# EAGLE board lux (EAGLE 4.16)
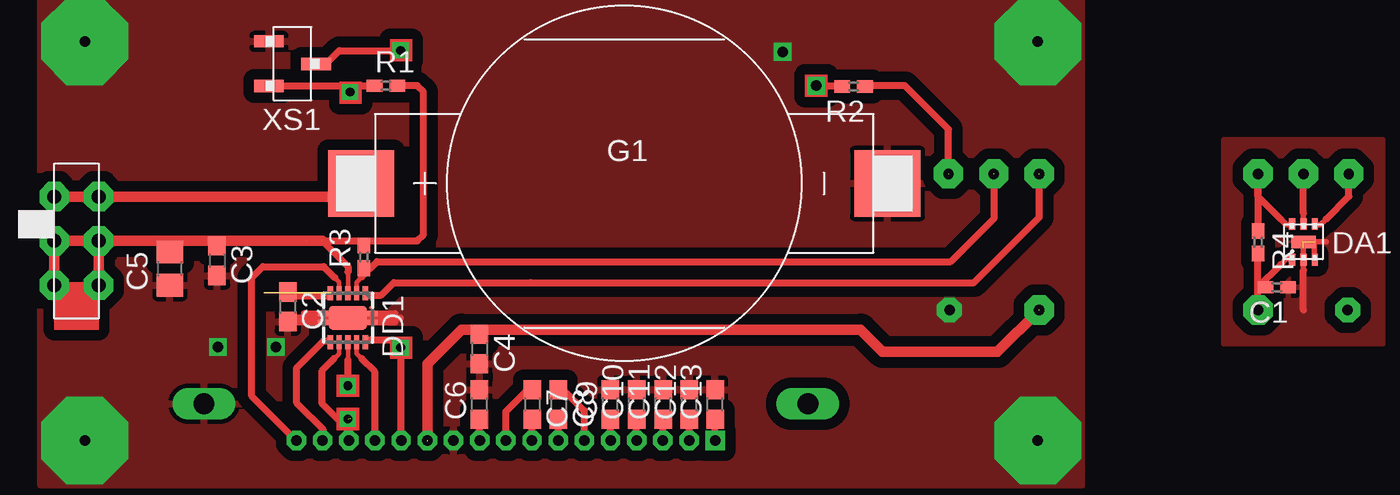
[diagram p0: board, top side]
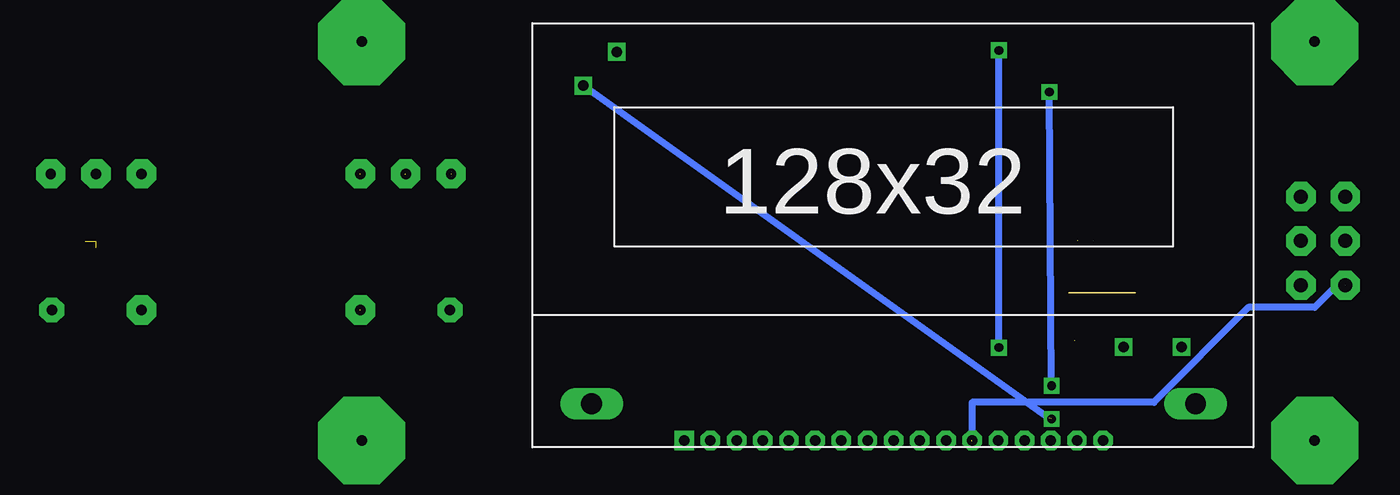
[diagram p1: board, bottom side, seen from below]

Size 3.81 x 0 mm. Coordinates in mm from the lower left corner, seen from the top.
Outline: 0,0 3.81,0
Copper layers (1*16): Top 0.035mm / dielectric 1.5mm / Bottom 0.035mm
Design rules "default": minimum track width 10mil, minimum drill 24mil, track to track 8mil, track to pad 8mil, pad to pad 8mil, via to via 8mil, smd to smd 8mil, copper to edge 40mil, drill to drill 8mil, minimum pad ring 10mil, minimum via ring 8mil, stop-mask expansion 4mil, vias tented up to drill 0mil, thermal gap 10mil

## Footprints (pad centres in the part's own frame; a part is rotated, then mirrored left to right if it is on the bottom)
C0402 = smd 0.9 x 0.7: 1 -0.65,0; 2 0.65,0
C0603 = smd 1.1 x 1: 1 -0.85,0; 2 0.85,0
C0805 = smd 1.3 x 1.5: 1 -0.95,0; 2 0.95,0
MLP11 = smd 0.8 x 0.3: 1 -1.4,1; 2 -1.4,0.5; 3 -1.4,0; 4 -1.4,-0.5; 5 -1.4,-1; 6 1.4,-1; 7 1.4,-0.5; 8 1.4,0; 9 1.4,0.5; 10 1.4,1 | smd 1.36 x 2.2: G 0,0 | smd 0.3 x 0.8: G1 -0.25,1.3; G2 0.25,1.3; G3 -0.25,-1.3; G4 0.25,-1.3
C12832 = drill 0.6 square: 1 -12,0 | drill 0.6 octagon: 2 -10.5,0; 3 -9,0; 4 -7.5,0; 5 -6,0; 6 -4.5,0; 7 -3,0; 8 -1.5,0; 9 0,0; 10 1.5,0; 11 3,0; 12 4.5,0; 13 6,0; 14 7.5,0; 15 9,0; 16 10.5,0; 17 12,0 | drill 1.2 long: 18 17.3,2.1; 19 -17.3,2.1
6UTDFN = smd 0.68 x 0.36: P$1 -1.025,0.65; P$2 -1.025,0; P$3 -1.025,-0.65; P$4 1.025,-0.65; P$5 1.025,0; P$6 1.025,0.65 | smd 0.71 x 1.4: P$7 0,0
CR2032 = smd 3.8 x 3.8: P$2 0,15.081; P$3 0,-15.081
SLIDER3 = drill 0.8 pad 1.676 octagon: P$1 0,1.27; P$2 -2.54,1.27; P$3 2.54,1.27; P$4 2.54,-1.27; P$5 0,-1.27; P$6 -2.54,-1.27
HEADER3S = smd 0.7 x 1.7: P$1 1.27,1.35; P$3 -1.28,1.35; P$4 -0.03,-1.35

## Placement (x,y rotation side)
C1  GND  [C0402]  not placed on the board
C2  [C0603]  1.35,-0.79 270 top
C3  [C0603]  -2.7,1.85 270 top
C4  [C0603]  not placed on the board
C5  [C0805]  not placed on the board
C6  [C0603]  not placed on the board
C7  [C0603]  not placed on the board
C8  [C0603]  not placed on the board
C9  [C0603]  not placed on the board
C10  [C0603]  not placed on the board
C11  [C0603]  not placed on the board
C12  [C0603]  not placed on the board
C13  [C0603]  not placed on the board
DD1  [MLP11]  4.8,-1.43 270 top
E$1  [C12832]  13.85,-8.45 0 bottom  (outside the outline)
E$12  [6UTDFN]  not placed on the board
E$43  [CR2032]  not placed on the board
E$44  [SLIDER3]  -10.76,2.98 270 top  (outside the outline)
R1  [C0402]  not placed on the board
R2  [C0402]  not placed on the board
R3  [C0402]  5.71,2.06 90 top
R4  [C0402]  not placed on the board
XS1  [HEADER3S]  not placed on the board

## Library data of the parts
C1-C13 R1-R4 = rcl
DD1 = silabs
E$1 = display-lcd
E$12 = maxim
E$43 E$44 XS1 = sb

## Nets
GND: C2.2 C3.2 C4.2 C5.1 C6.2 C9.2 C10.2 C11.2 C12.2 C13.2 E$1.11 E$1.18 E$43.P$2 XS1.P$1
GND2: C1.1 E$12.P$7
PWR: E$44.P$3 E$44.P$4
S$1: E$1.9
S$22: XS1.P$3

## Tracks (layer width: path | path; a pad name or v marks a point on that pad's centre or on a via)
GND  (via drill 0.6, 0.6 pad 1.42, 0.6 pad 5)
  Top 0.406: 7.48,-1.67 4.8,-1.67 1.86,-1.67 | 1.59,-1.43 7.82,-1.43 | 2.3,-1.19 7.48,-1.19
  other vias: -10.28,-8.45 39.27,-0.98 -10.28,14.41 44.33,-8.45 44.33,14.41 -2.66,-3.1 0.67,-3.1 29.73,13.81
  pour Top (isolate 0.61): 46.87,-10.99 46.87,16.95 -12.82,16.95 -12.82,-10.99
GND2  (2 unrouted)
  Top 0.305: 60.19,2.92 60.19,1.77 | 59.55,1.3 59.55,2.6 | 59.16,2.92 60.85,2.92
  Top 0.406: 59.55,-0.98 59.55,1.3
  pour Top (isolate 0.61): 64.1,-2.93 55,-2.93 55,8.77 64.1,8.77
GND3  (via drill 0.6 pad 1.42)
  other vias: 62.09,-0.98
PWR  (via drill 0.6 pad 1.68)  (5 unrouted)
  Top 0.254: 4.8,1.19 4.8,-0.28
  Top 0.406: 7.46,11.87 8.77,11.87 9.13,11.51 9.13,3.33 8.77,2.98 | 4.8,1.51 4.8,1.19 | 8.77,2.98 | 3.29,2.98 8.77,2.98 | 4.8,1.51 | 4.8,1.51 3.33,2.98 | E$44.P$4 E$44.P$3
  Top 0.61: 44.41,-0.99 42.03,-3.37 35.44,-3.37 34.17,-2.1 11.31,-2.1 9.37,-4.05 9.37,-8.45 | 3.33,2.98 2.42,2.98 -9.49,2.98 | E$44.P$3 -9.49,2.98 | -9.49,2.98 -12.03,2.98 E$44.P$4
  Bottom 0.406: 9.37,-8.49 9.37,-7.98 9.37,-6.27 -1.07,-6.27 -6.47,-0.83 -10.28,-0.83 -11.55,0.44 E$44.P$4
  other vias: 44.41,-0.98
PWR1  (via drill 0.6 pad 1.68)
  Top 0.305: 58.9,1.95 58.58,1.95 58.25,1.62
  Top 0.406: v56.95,-0.98 56.95,0.32 | 56.95,0.32 58.25,1.62 | 56.95,0.32 56.95,2.24
S$1
  Top 0.406: E$1.9 13.85,-6.79 15.12,-5.52
S$2
  Top 0.406: 15.36,-8.45 15.36,-7.34
S$3
  Top 0.406: 16.87,-8.45 16.87,-7.34
S$4
  Top 0.406: 18.34,-8.45 18.34,-6.75 17.18,-5.6 16.87,-5.6
S$5
  Top 0.406: 19.84,-8.45 19.84,-7.18
S$6
  Top 0.406: 21.35,-8.45 21.35,-7.18
S$7
  Top 0.406: 22.86,-8.45 22.86,-7.18
S$8
  Top 0.406: 24.37,-8.45 24.37,-7.18
S$9
  Top 0.406: 25.84,-8.45 25.84,-7.14
S$10
  Top 0.406: 12.34,-8.45 12.34,-7.18
S$11
  Top 0.406: 1.39,-0.16 3.65,-0.16
S$12
  Top 0.406: -0.08,11.87 6.07,11.87
S$13
  Top 0.254: 4.8,-3.85 4.8,-2.7
  Top 0.406: 4.8,-4.84 4.8,-3.85
S$14
  Top 0.254: 5.93,-2.7 6.19,-2.7 5.79,-2.7
  Top 0.406: 5.93,-2.7 6.91,-2.7 7.86,-2.7 7.86,-3.21 7.86,-8.45
S$15
  Top 0.406: 3.85,-3.93 3.33,-4.45 3.33,-6.35 4.84,-7.86 4.84,-8.45
S$16
  Top 0.254: 5.6,-3.77 5.3,-3.47 5.3,-2.74
  Top 0.406: 5.6,-3.77 6.35,-4.52 6.35,-8.45
S$17
  Top 0.406: 2.98,13.1 3.53,13.1 4.31,13.87 7.9,13.87
S$18  (via drill 0.6 pad 1.68)
  Top 0.305: 60.2,3.9 60.53,3.9 60.85,4.22
  Top 0.406: v62.15,6.82 62.15,5.52 60.85,4.22
S$19  (via drill 0.6 pad 1.68)  (1 unrouted)
  Top 0.406: 44.41,6.79 44.41,4.33 41.79,1.71 40.68,0.6 15.28,0.6 7.42,0.6 6.67,-0.16 5.95,-0.16
  other vias: 44.41,6.82
S$20  (via drill 0.6 pad 1.68)  (1 unrouted)
  Top 0.406: 34.69,11.87 36.71,11.87 39.21,9.37 39.21,6.79
  other vias: 39.21,6.82
S$21
  Top 0.254: 4.31,-0.24 4.31,0.38 4.31,0.62 4.05,0.87
  Top 0.406: 4.05,0.87 | 4.05,0.87 3.41,1.51 -0.08,1.51 -0.71,0.87 -0.71,-5.91 1.86,-8.49
S$23  (via drill 0.6 pad 1.68)  (1 unrouted)
  Top 0.254: 5.3,-0.28 5.3,0.62 5.6,0.91
  Top 0.406: 41.83,6.79 41.83,4.29 39.35,1.79 39.33,1.79 6.47,1.79 5.6,0.91
  other vias: 41.81,6.82
S$24  (via drill 0.5)
  other vias: 4.92,11.51
S$25  (1 unrouted)
  Top 0.254: 3.71,-2.74 3.41,-2.74 | 3.81,-2.7 3.45,-2.7
  Top 0.406: 3.71,-2.74 3.45,-2.74 3.41,-2.74 1.86,-4.29 1.86,-6.31 | 1.86,-6.31 3.37,-7.82 3.37,-8.14 3.37,-8.45 | 1.86,-6.31
S$26
  Top 0.254: 4.31,-2.74 4.31,-3.47 4.01,-3.77
S$27
  Top 0.406: 3.85,-3.93 4.01,-3.77
S$28  (via drill 0.5)
  other vias: 4.8,-5.32
S$29  (via drill 0.6 pad 1.68)
  Top 0.305: 59.55,3.9 59.55,4.55
  Top 0.406: 59.55,4.55 v59.55,6.82
S$30  (via drill 0.5)
  other vias: 7.82,13.89
S$31  (via drill 0.6 pad 1.68)
  Top 0.305: 58.9,3.9 58.58,3.9 58.25,4.22
  Top 0.406: 56.95,5.99 56.95,3.45 | 56.95,5.99 v56.95,6.82 | 56.95,5.99 56.95,5.52 58.25,4.22
S$33
  Bottom 0.406: 4.8,-5.36 4.92,11.47
S$34  (via drill 0.5, 0.6)  (1 unrouted)
  Top 0.406: v31.63,11.87 32.9,11.87
  Bottom 0.406: 4.96,-7.18 v31.63,11.87
  other vias: 4.8,-7.22
S$38  (via drill 0.5)
  other vias: 7.82,-3.14
S$75
  Top 0.61: -12.03,5.52 3.69,5.52
S$78
  Bottom 0.406: 7.82,-3.1 7.82,13.85
(copper drawn outside any net)
  shapes: Top area x7

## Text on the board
tNames: XS1 | G1 | DA1
tDocu: CS | RST | A0 | SCL | SDA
